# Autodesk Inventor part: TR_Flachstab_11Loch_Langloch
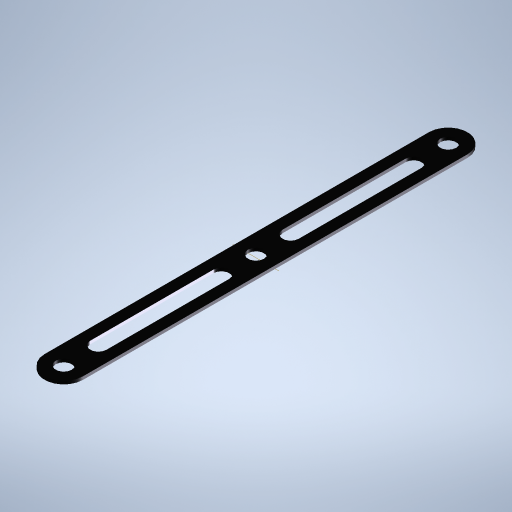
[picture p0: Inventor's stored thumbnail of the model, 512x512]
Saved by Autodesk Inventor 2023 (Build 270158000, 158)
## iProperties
Created: 2023-11
Part Number: TR_Flachstab_11Loch_Langloch
Material: Edelstahl
Document SubType Name: Modeling
Designer: Admin
Density: 8 g/cm^3
Appearance: Halbpoliert
Author: Admin
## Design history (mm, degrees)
sketch "Skizze1"
  geometry: L1 (0, 50)-(0, -50); L2 (-5, 50)-(-5, -50); L3 (5, -50)-(5, 50); A1 r 5 centre (0, 50) between (5, 50) and (-5, 50); A2 r 5 centre (0, -50) between (-5, -50) and (5, -50); 3 further points
  constraints: 8 end point, 4 point on circle, 4 tangent, 2 centre point, 2 midpoint, 1 horizontal alignment, 1 parallel, 1 vertical, 1 vertical alignment
  dimensions: "d0" = 100 distance of L1.start L1.end (computed from Loch, Einheitsmaß); "d1" = 5 radius of A1 (= 0.5 x Einheitsmaß)
extrude "Extrusion1" new body sketch "Skizze1" distance "d5" = 0.8 (= Dicke); taper "d6" = 0 deg
sketch "Skizze2"
  geometry: L1 (0, 41)-(0, 9); L2 (-2.075, 41)-(-2.075, 9); L3 (2.075, 9)-(2.075, 41); L4 (0, 50)-(0, 41); L5 (0, 9)-(0, 0); C1 r 2.075 at (0, 50); C2 r 2.075 at (0, 0); A1 r 5 centre (0, 50) between (5, 50) and (-5, 50) reference; A2 r 5 centre (0, -50) between (-5, -50) and (5, -50) reference; A3 r 2.075 centre (0, 41) between (2.075, 41) and (-2.075, 41); A4 r 2.075 centre (0, 9) between (-2.075, 9) and (2.075, 9); 3 further points
  constraints: 12 end point, 4 centre point, 4 point on circle, 4 tangent, 2 coincident, 2 equal length, 2 midpoint, 2 vertical, 1 collinear, 1 equal radius, 1 point on line
  dimensions: "d7" = 4.15 diameter of C1 (= 2 x Radius); "d14" = 32 distance of L1.start L1.end; "d15" = 4.15 diameter of C2 (= 2 x Radius)
extrude "Extrusion2" cut sketch "Skizze2" stored distance "d8" = 10; taper "d9" = 0 deg
mirror "Spiegeln1"
node "Volumenkörper1"
other parameters: "Radius" = 2.075 [user parameter; used in 2 equation terms], "Fasen" = 0.5 [user parameter], "Dicke" = 0.8 [user parameter; used in 1 equation term]
